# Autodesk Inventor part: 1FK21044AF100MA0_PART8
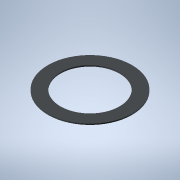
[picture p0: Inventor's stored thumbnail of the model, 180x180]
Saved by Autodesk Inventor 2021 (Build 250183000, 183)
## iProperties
Created: 2025-04
Part Number: 1FK21044AF100MA0_PART8
Material: Generic
Catalog Web Link: www.3dfindit.com
Description: -Servo synchronous motor
Document SubType Name: Modeling
Designer: psAdmin
Mass: 0.27214 g
Surface Area: 11.8752 cm^2
Volume: 0.27214 cm^3
Density: 1 g/cm^3
Appearance: PSOLRGB-212-217-219
Category: PARTsolutions
Title: 1FK21044AF100MA0_PART8
Author: Cadenas PARTsolutions
Comments: Servo synchronous motor
Sending System: PARTsolutions
Preprocessor: ST-DEVELOPER v19.3
PSOL_IDENT_0: {$CADENAS_DATA/23d-libs/siemens_ag/_cat_/ec/e4/1fk21044af100ma0.prj},213 {VTYP=3D},{NB=1FK21044AF100
PSOL_IDENT_1: MA0_PART8},{LINA=1FK21044AF100MA0_PART8},{NN=1FK21044AF100MA0_PART8},{NOPRJ=TRUE},{DATE=19.08.2025 1
PSOL_IDENT_2: 4:01:05},{GEOMDATE=30.07.2025 02:01:01},{VERSION=},{LINEID=10},{WBVAR=},{WBNUMERIC=}  {NB=1FK21044AF
PSOL_IDENT_3: 100MA0_PART8},{LINA=1FK21044AF100MA0_PART8},{KT=DUMMY},{PREVIEW=../../../_pool_/cb/72/p_d211_xx_0043
PSOL_IDENT_4: 4j.png},{DESCSHORT=SIMOTICS S-1FK2 HD, SINAMICS S210 3AC 400V-480V, 1.27 Nm, 3000 rpm},{DESCLONG=SIM
PSOL_IDENT_5: OTICS S-1FK2 HD servo motor M0=1.27 Nm; PN = 0.4 kW at nN=3000 rpm (380-480 V); PN = 0.2 kW at nN=15
PSOL_IDENT_6: 00 rpm (200-240 V); with holding brake; degree of protection IP64; cylindrical shaft D19x40mm; absol
PSOL_IDENT_7: ute encoder 22-bit + 12-bit multiturn (encoder AM22DQC); with OCC interface; plug size M17, rotatabl
PSOL_IDENT_8: e; SIMOTICS S-1FK2 servomotorfor a wide range of uses in industrial environments. SIMOTICS S‑1FK2 se
PSOL_IDENT_9: rvomotors are compact synchronous motors with a high dynamic performance that set themselves apart a
PSOL_IDENT_10: s a result of their high power density, degree of protection and overload capability. The motors are
PSOL_IDENT_11: available in two variants: as High Dynamic variant (highest dynamic performance as a result of the
PSOL_IDENT_12: low intrinsic moment of inertia for applications demanding a high dynamic performance with low moved
PSOL_IDENT_13: masses) - and as Compact variant (precise and stable closed-loop control for medium up to large mov
PSOL_IDENT_14: ed masses as a result of a medium intrinsic moment of inertia). SIMOTICSS‑1FK2 servomotors fully exp
PSOL_IDENT_15: loit their strengths in a system with the SINAMICSS210 frequency converter and simple connection usi
PSOL_IDENT_16: ng the one cable connection (OCC). Advantages include the short control and positioning times, fast
PSOL_IDENT_17: and precise correction of disturbing quantities as well as stable control with a high dynamic perfor
PSOL_IDENT_18: mance. The servo motors can be configured to address a wide range of requirements. For example with
PSOL_IDENT_19: and without holding brake, IP64 or IP65 degree of protection, singleturn or multiturn absolute encod
PSOL_IDENT_20: ers - to name just a few. Further, the servomotors are available in different shaft heights extendin
PSOL_IDENT_21: g from 20 to 100. A shaft sealing ring is available to achieve an IP65 degree of protection and for
PSOL_IDENT_22: subsequent mounting at the motor or as spare part. SIMOTICS - the optimum motor for each and every m
PSOL_IDENT_23: otion control application.},{INTNO=195125043275},{SUPPLIERALTNO=1FK2104-4AF10-0MA0},{MANUID=1FK21044
PSOL_IDENT_24: AF100MA0},{MANUNAME=Siemens},{MANUTYPEDESC=Synchronous motor 1FK2-HD 1.27 NM},{AAU732=SIMOTICS},{AAO
PSOL_IDENT_25: 057=S-1FK2},{AAU734=SIMOTICS S-1FK2 HD servo motor M0=1.27 Nm; PN = 0.4 kW at nN=3000 rpm (380-480 V
PSOL_IDENT_26: ); PN = 0.2 kW at nN=1500 rpm (200-240 V); with holding brake; degree of protection IP64; cylindrica
PSOL_IDENT_27: l shaft D19x40mm; absolute encoder 22-bit + 12-bit multiturn (encoder AM22DQC); with OCC interface;
PSOL_IDENT_28: plug size M17, rotatable;},{AAW338=Synchronous motor 1FK2-HD 1.27 NM},{AAO742=SIMOTICS},{AAO663=4042
PSOL_IDENT_29: 948694015},{NOCUPEROU=1},{PRICEQUANTITY=1},{QUANTITYMIN=1},{QUANTITYINT=1},{CTN=85015100},{COO=DE},{
PSOL_IDENT_30: AAO676=1FK2104-4AF10-0MA0},{AAO677=Siemens AG},{ORDERUNIT=C62},{CONTENTUNIT=C62}
NB: 1FK21044AF100MA0_PART8
NT: Servo synchronous motor
NBSYN: $MANUID._PART8
LINA: 1FK21044AF100MA0_PART8
CATALOG: SIEMENS
PREVIEW: ../../../_pool_/cb/72/p_d211_xx_00434j.png
DESCSHORT: SIMOTICS S-1FK2 HD, SINAMICS S210 3AC 400V-480V, 1.27 Nm, 3000 rpm
DESCLONG: SIMOTICS S-1FK2 HD servo motor M0=1.27 Nm; PN = 0.4 kW at nN=3000 rpm (380-480 V); PN = 0.2 kW at nN=1500 rpm (200-240 V); with holding brake; degree of protect
INTNO: 195125043275
SUPPLIERALTNO: 1FK2104-4AF10-0MA0
MANUID: 1FK21044AF100MA0
MANUNAME: Siemens
MANUTYPEDESC: Synchronous motor 1FK2-HD 1.27 NM
AAU732: SIMOTICS
AAO057: S-1FK2
AAU734: SIMOTICS S-1FK2 HD servo motor M0=1.27 Nm; PN = 0.4 kW at nN=3000 rpm (380-480 V); PN = 0.2 kW at nN=1500 rpm (200-240 V); with holding brake; degree of protect
AAW338: Synchronous motor 1FK2-HD 1.27 NM
AAO742: SIMOTICS
AAO663: 4042948694015.0
NOCUPEROU: 1
PRICEQUANTITY: 1
QUANTITYMIN: 1
QUANTITYINT: 1
CTN: 85015100
COO: DE
ARTICLENO: 1FK21044AF100MA0_PART8
BOMINFO: 1FK21044AF100MA0_PART8
CREATOR: CADENAS GmbH
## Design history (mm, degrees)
feature "2025_04_17_15_33_01_0673"
body "Solid1"
